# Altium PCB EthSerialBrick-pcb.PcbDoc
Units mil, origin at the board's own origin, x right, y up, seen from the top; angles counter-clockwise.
Board outline 3550 x 3775 mil, 4 copper layers (Top Layer, Internal Plane 1, Internal Plane 2, Bottom Layer); 26 components, 31 nets, 202 pads, 3 vias.
Unrouted connection lines stored in the file: 30.
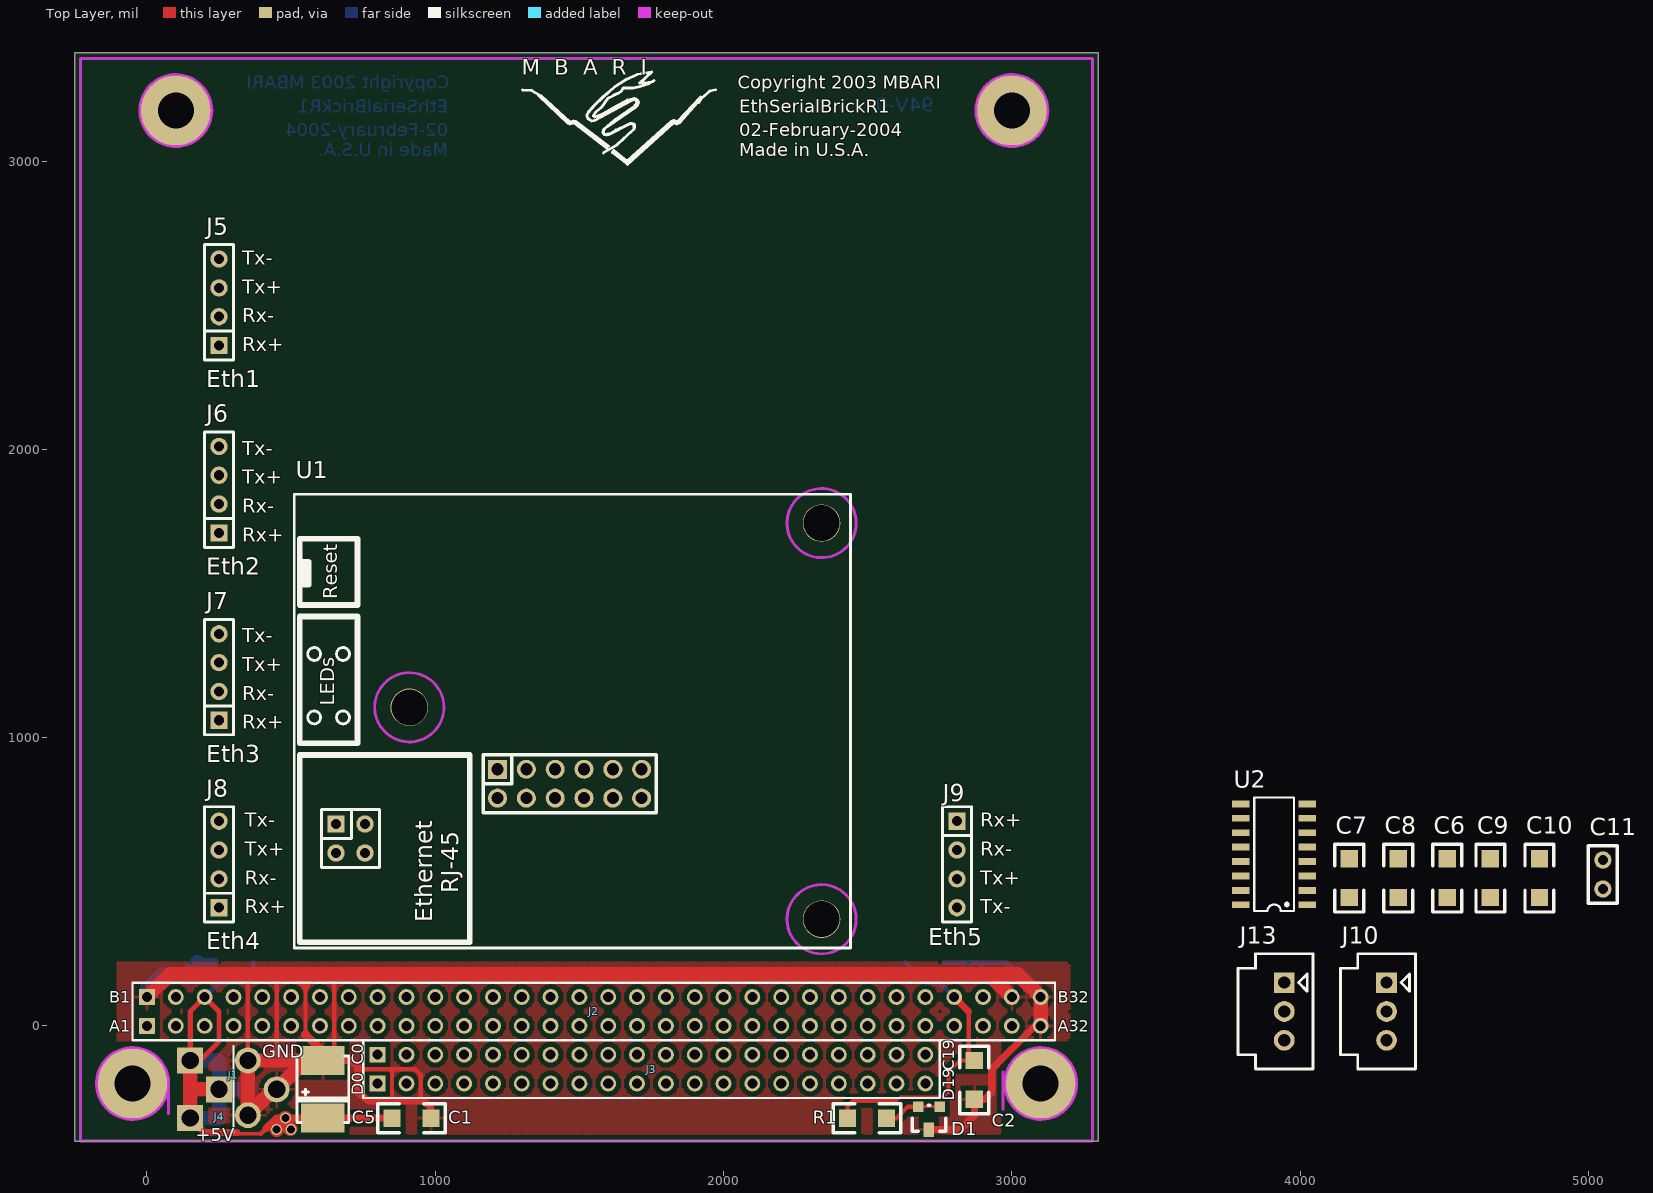
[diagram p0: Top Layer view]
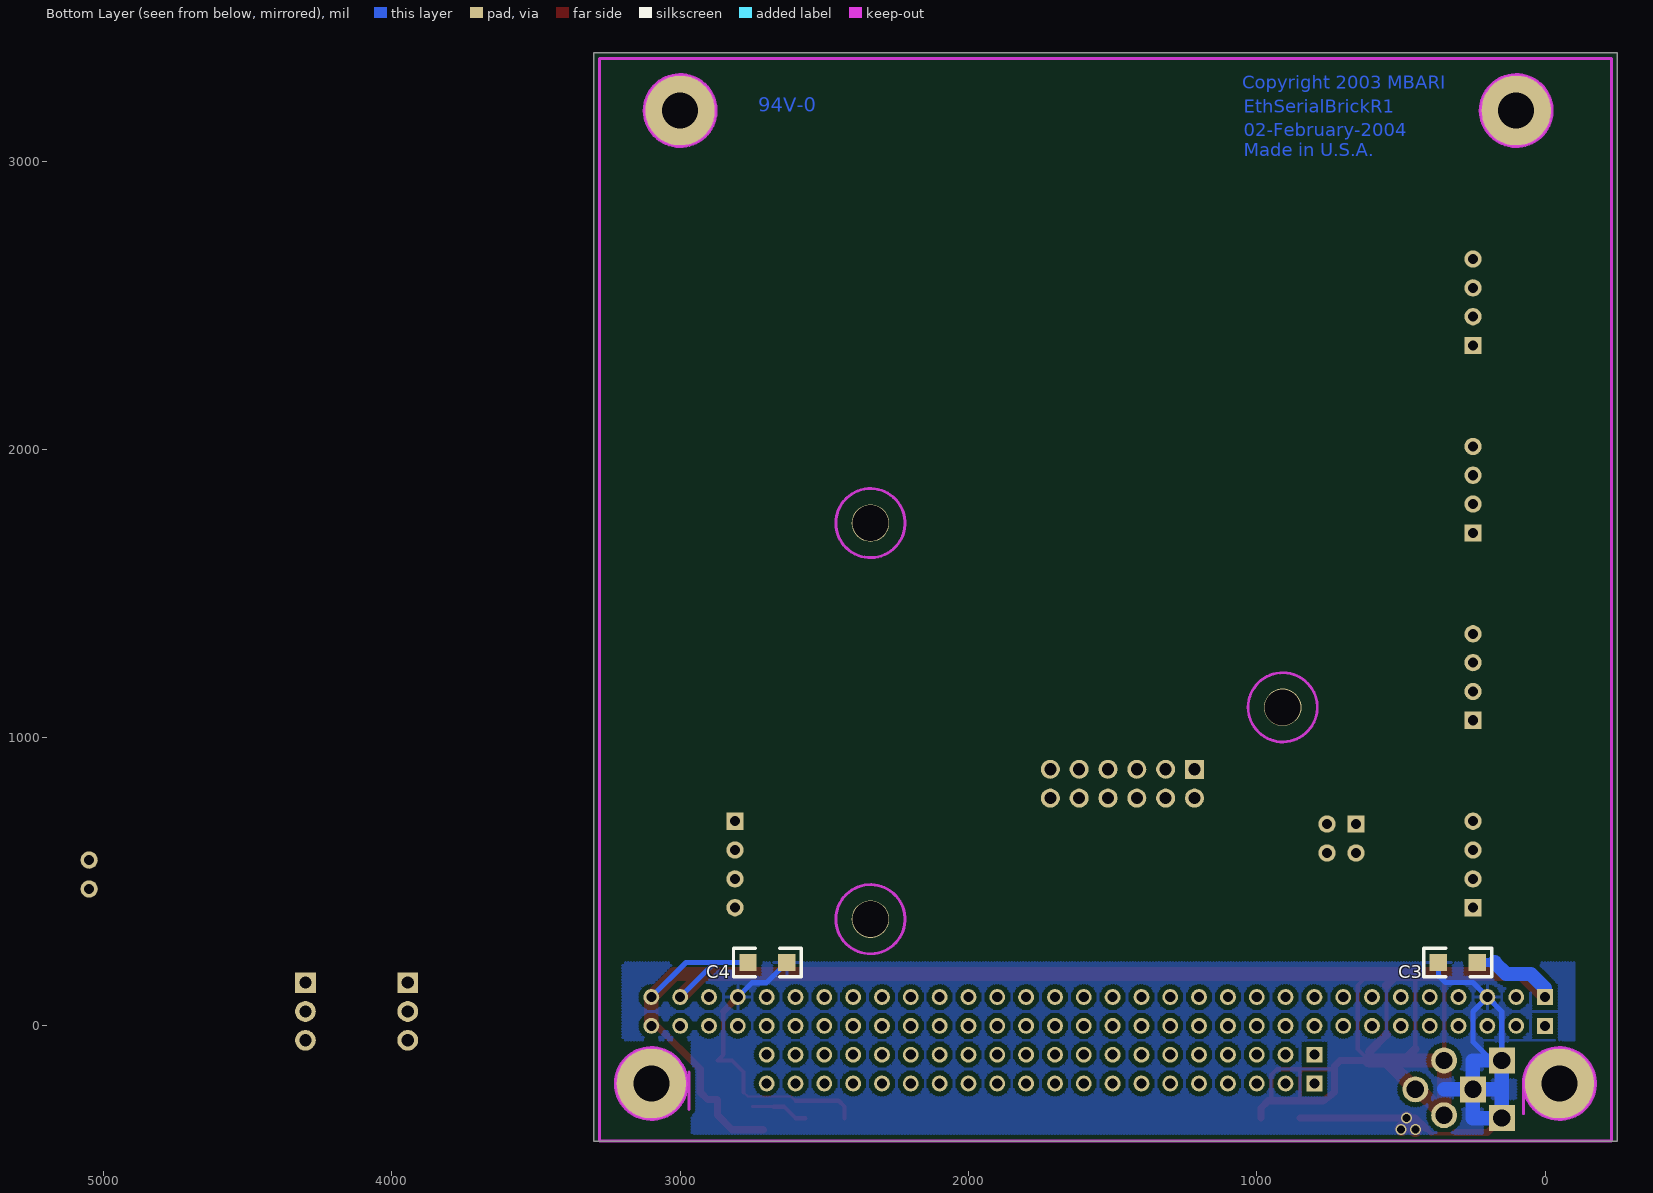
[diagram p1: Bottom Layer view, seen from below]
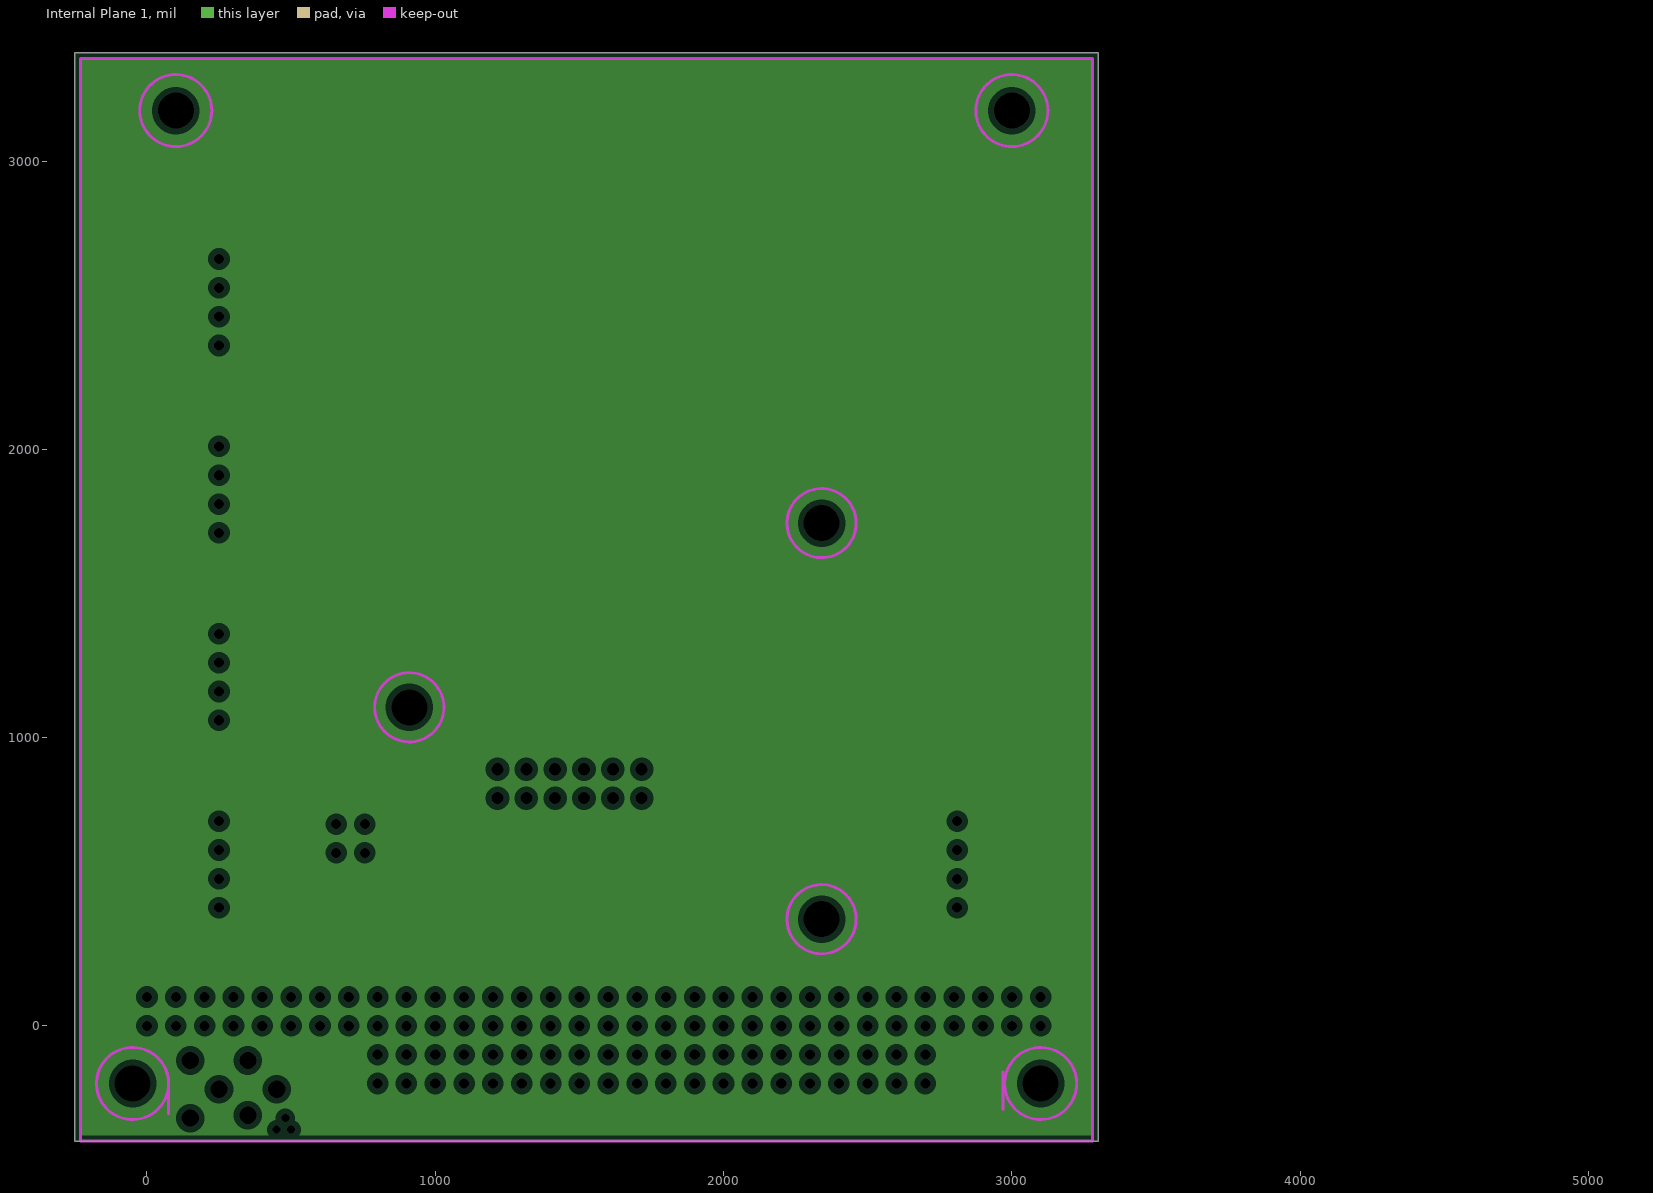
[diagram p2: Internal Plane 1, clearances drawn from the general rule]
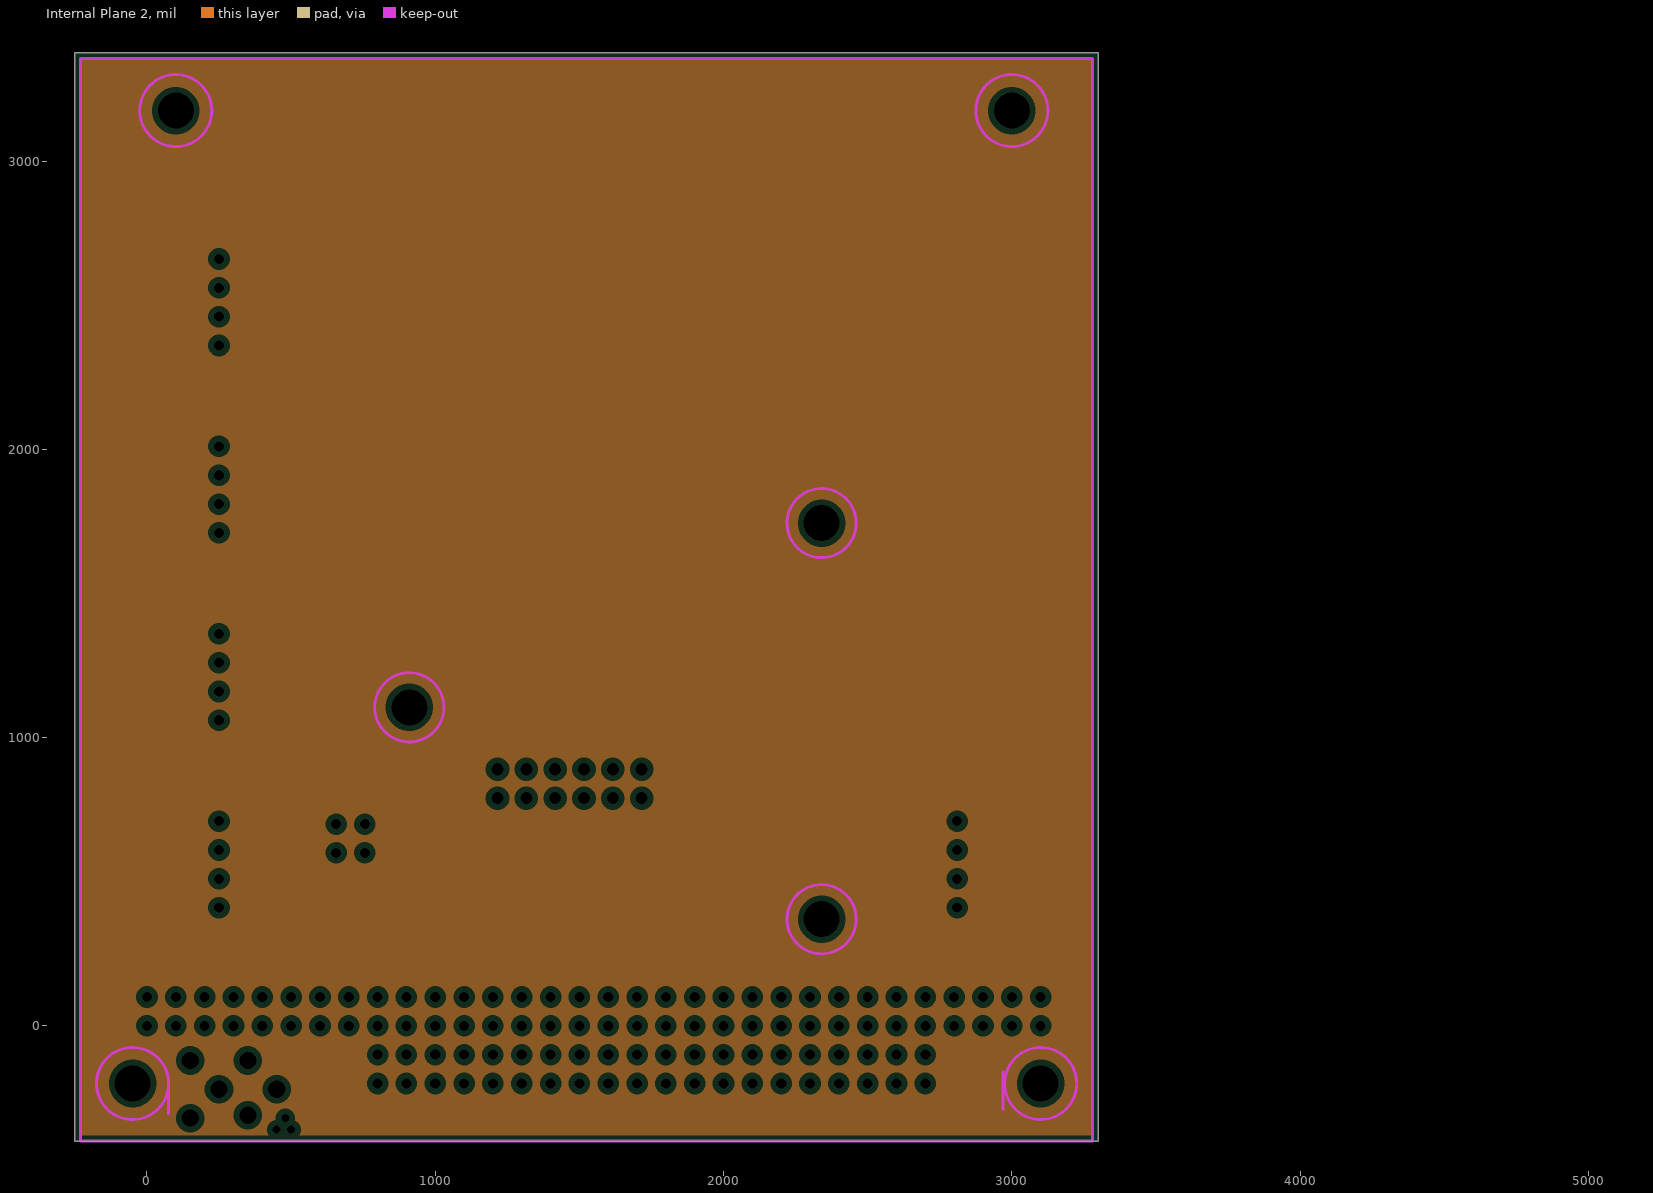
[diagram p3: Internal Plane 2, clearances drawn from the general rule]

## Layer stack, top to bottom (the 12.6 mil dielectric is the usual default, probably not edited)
Top Layer: signal copper 1.4
Dielectric: dielectric 12.6, FR-4, Dk 4.8
Internal Plane 1: plane copper 1.4
Dielectric: dielectric 12.6, FR-4, Dk 4.8
Internal Plane 2: plane copper 1.4
Dielectric: dielectric 12.6, FR-4, Dk 4.8
Bottom Layer: signal copper 1.4

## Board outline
-250,-400 -250,3375 3300,3375 3300,-400

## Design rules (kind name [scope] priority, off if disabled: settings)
Clearance Clearance_poly [InPolygon] p1: gap=16 // poly
Clearance [All] p2: gap=13
ComponentClearance [All] p1: gap=10 collisioncheckmode=0
FanoutControl Fanout_Small [(CompPinCount < 5)] p1: bgadir=Out bgaviamode=Centered fanoutstyle=Auto fanoutdirection=OutThenIn viagrid=1 // Fanout_Small (Default Rule)
FanoutControl Fanout_Default [All] p2: bgadir=Out bgaviamode=Centered fanoutstyle=Auto fanoutdirection=Alternating viagrid=1 // Fanout_Default (Default Rule)
FanoutControl Fanout_BGA [IsBGA] p4: bgadir=Out bgaviamode=Centered fanoutstyle=Auto fanoutdirection=Alternating viagrid=1 // Fanout_BGA (Default Rule)
FanoutControl Fanout_LCC [IsLCC] p5: bgadir=Out bgaviamode=Centered fanoutstyle=Auto fanoutdirection=Alternating viagrid=1 // Fanout_LCC (Default Rule)
HoleSize [All] p1: absolutevalues=TRUE maxlimit=152 minlimit=1 maxpercent=80.000 minpercent=20.000
PlaneClearance [All] p1: clearance=20
PlaneConnect [All] p1: planeconnectstyle=Relief reliefexpansion=20 reliefentries=4 reliefconductorwidth=10 reliefairgap=10
PolygonConnect [All] p1: connectstyle=Relief reliefconductorwidth=10 reliefentries=4 polygonreliefangle="90 Angle"
RoutingLayers [All] p1: top layer=Horizontal bottom layer=Vertical
RoutingVias [All] p1: holewidth=35 width=52 viastyle="Through Hole" minholewidth=28 minwidth=32 maxholewidth=86 maxwidth=72
SolderMaskExpansion [All] p1: expansion=4
TestPointUsage [All] p1: valid=0 allowmultiple=FALSE
Testpoint [All] p1: side=15 testpointundercomponent=TRUE minsize=40 maxsize=100 preferedsize=60 minholesize=0 maxholesize=40 preferedholesize=32 testpointgrid=1 style=1023 order=-539222988
Width [All] p1: maxlimit=250 minlimit=8 preferedwidth=12 toplayer_prefwidth=15 bottomlayer_prefwidth=50 minimp=50.000000 maximp=50.000000 favimp=50.000000
9 further rules are at their usual default settings.

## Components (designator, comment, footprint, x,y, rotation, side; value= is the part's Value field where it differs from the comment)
C1 "0.1uF" 1206 850,-320 r0 top
C2 "0.1uF" 1206 2870,-120 r270 top
C3 "0.1uF" 1206 370,220 r180 bottom
C4 "0.1uF" 1206 2630,220 r0 bottom
C5 "47uF" 6032POL 610,-320 r90 top
C6 "0.1uF" 1206 4510,445 r90 top
C7 "0.1uF" 1206 4170,445 r90 top
C8 "0.1uF" 1206 4340,445 r90 top
C9 "0.1uF" 1206 4660,445 r90 top
C10 "0.1uF" 1206 4830,445 r90 top
C11 "0.1uF" RAD0.1 5050,475 r90 top
D1 "LED" SOT-23 2750,-280 r180 top
J1 "Power" SIP4#1 150,-120 r0 top
J2 "PC104-AB" PC104-AB 0,0 r0 top locked
J3 "PC104-CD" PC104-CD 800,-200 r0 top locked
J4 "PowHD" SIP2 225,-765 r90 top
J5 "Eth1" SIP4#2 250,2360 r90 top locked
J6 "Eth2" SIP4#2 250,1710 r90 top locked
J7 "Eth3" SIP4#2 250,1060 r90 top locked
J8 "Eth4" SIP4#2 250,410 r90 top locked
J9 "Eth5" SIP4#2 2810,710 r270 top locked
J10 "Ser1" CGRID3 4300,150 r90 top
J13 "Ser2" CGRID3 3945,150 r90 top
R1 "510" 1206 2430,-320 r0 top
U1 "COBOX-MICRO" COBOX-MICRO 2440,270 r90 top
U2 "MAX232" SOIC-16-0.15W 4025,420 r90 top

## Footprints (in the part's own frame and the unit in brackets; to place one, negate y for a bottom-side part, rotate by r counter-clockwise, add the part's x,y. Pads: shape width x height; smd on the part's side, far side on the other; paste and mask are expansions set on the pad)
1206 [mil]
  rect 60x60 smd: 1(0,0) 2(135,0)
  silkscreen extent -50,-50 185,50
6032POL [mil]
  rect 100x150 smd: 1(0,0) 2(200,0)
  silkscreen extent -15,-90 215,90
CGRID3 [mil]
  rect 72x72 hole 42: 1(0,0)
  round 72 hole 42: 2(-100,0) 3(-200,0)
  silkscreen extent -300,-100 100,160
COBOX-MICRO [mil]
  round 130 hole 125: 0(100,100) 0(835,1530) 0(1474,100)
  rect 66x66 hole 42: 1(620,1224)
  round 66 hole 42: 2(520,1224) 3(620,1124) 4(520,1124) 5(620,1024) 6(520,1024) 7(620,924) 8(520,924) 9(620,824) 10(520,824) 11(620,724) 12(520,724)
  rect 60x60 hole 35: 21(430,1784)
  round 60 hole 35: 22(430,1684) 23(330,1784) 24(330,1684)
  Keep-Out Layer circle w10: c835,1530 r120
  Keep-Out Layer circle w10: c1474,100 r120
  Keep-Out Layer circle w10: c100,100 r120
  silkscreen extent 0,0 1574,1929
PC104-AB [mil] "PC/104 A&B rails"
  rect 55x55 hole 35: A1(0,0) B1(0,100)
  round 55 hole 35: A2(100,0) A3(200,0) A4(300,0) A5(400,0) A6(500,0) A7(600,0) A8(700,0) A9(800,0) A10(900,0) A11(1000,0) A12(1100,0) A13(1200,0) A14(1300,0) A15(1400,0) A16(1500,0) A17(1600,0) A18(1700,0) A19(1800,0) A20(1900,0) A21(2000,0) A22(2100,0) A23(2200,0) A24(2300,0) A25(2400,0) A26(2500,0) A27(2600,0) A28(2700,0) A29(2800,0) A30(2900,0) A31(3000,0) A32(3100,0) B2(100,100) B3(200,100) B4(300,100) B5(400,100) B6(500,100) B7(600,100) B8(700,100) B9(800,100) B10(900,100) B11(1000,100) B12(1100,100) B13(1200,100) B14(1300,100) B15(1400,100) B16(1500,100) B17(1600,100) B18(1700,100) B19(1800,100) B20(1900,100) B21(2000,100) B22(2100,100) B23(2200,100) B24(2300,100) B25(2400,100) B26(2500,100) B27(2600,100) B28(2700,100) B29(2800,100) B30(2900,100) B31(3000,100) B32(3100,100)
  silkscreen extent -50,-50 3150,150
PC104-CD [mil] "PC/104 C&D rails"
  rect 55x55 hole 35: C0(0,100) D0(0,0)
  round 55 hole 35: C1(100,100) C2(200,100) C3(300,100) C4(400,100) C5(500,100) C6(600,100) C7(700,100) C8(800,100) C9(900,100) C10(1000,100) C11(1100,100) C12(1200,100) C13(1300,100) C14(1400,100) C15(1500,100) C16(1600,100) C17(1700,100) C18(1800,100) C19(1900,100) D1(100,0) D2(200,0) D3(300,0) D4(400,0) D5(500,0) D6(600,0) D7(700,0) D8(800,0) D9(900,0) D10(1000,0) D11(1100,0) D12(1200,0) D13(1300,0) D14(1400,0) D15(1500,0) D16(1600,0) D17(1700,0) D18(1800,0) D19(1900,0)
  silkscreen extent -50,-50 1950,150
RAD0.1 [mil]
  round 60 hole 35: 1(0,0) 2(100,0)
  silkscreen extent -50,-50 150,50
SIP2 [mil]
  rect 90x90 hole 59.5: 1(445,75)
  round 90 hole 59.5: 2(455,-125)
SIP4#1 [mil]
  rect 90x90 hole 59.5: 1(0,0) 2(100,-100)
  round 90 hole 59.5: 3(200,0) 4(300,-100)
  silkscreen extent 150,-150 150,50
SIP4#2 [mil]
  rect 60x60 hole 35: 1(0,0)
  round 60 hole 35: 2(100,0) 3(200,0) 4(300,0)
  silkscreen extent -50,-50 350,50
SOIC-16-0.15W [mm] "SOIC-16 0.15\"Wide 1.27mm Pitch"
  rect 0.6x1.55 smd: 1(0,0) 2(1.27,0) 3(2.54,0) 4(3.81,0) 5(5.08,0) 6(6.35,0) 7(7.62,0) 8(8.89,0) 9(8.89,5.85) 10(7.62,5.85) 11(6.35,5.85) 12(5.08,5.85) 13(3.81,5.85) 14(2.54,5.85) 15(1.27,5.85) 16(0,5.85)
  silkscreen extent -0.55,1.18 9.44,4.67
SOT-23 [mil]
  rect 36x36 smd: 1(0,0) 2(75,0)
  rect 36x50 smd: 3(38,80)
  silkscreen extent -20,-5 95,85

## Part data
C1 C2 C3 C4 C6 C7 C8 C9 C10: library part CAPACITOR, "Capacitor"
C5: library part "CAPACITOR POL", "Capacitor"
C11: library part Cap, "Capacitor"
J1: library part CON4, "Connector"
J2: "PC/104 A&B rails"
J3: "PC/104 C&D rails"
J4: library part CON2, "Connector"
J5 J6 J7 J8 J9: library part CON4, "Connector 4 pin"
J10 J13: library part CON3, "Connector"
R1: library part RESISTOR, "Resistor"
U1: "CoBox Micro Terminal Server"
U2: "MAX232 Communications Chip"

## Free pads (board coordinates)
  round 250 hole 125: 0(-50,-200) 0(100,3175) 0(3000,3175) 0(3100,-200)

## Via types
v1: diameter 38, hole 28, Top Layer to Bottom Layer, 3 vias

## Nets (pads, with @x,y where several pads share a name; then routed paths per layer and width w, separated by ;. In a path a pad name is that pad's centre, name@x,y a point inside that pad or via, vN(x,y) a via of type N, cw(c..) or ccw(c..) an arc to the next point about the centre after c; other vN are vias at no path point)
GND: C1.2 C2.2 C3.2 C4.2 C5.2 C7.2 C9.1 C11.1 D1.3 J1.3 J1.4 J2.A32 J2.B1 J2.B31 J2.B32 J4.2 J10.3 J13.3 U1.2 U2.15 | length 7957.3
  Top Layer w15: J1.3 350,180 ; 440,180 450,170 450,-80 ; 550,-30 550,140 ; C5.2@610,-90 C5.2 650,-80 650,140 610,180 ; 730,-150 840,-150 ; 850,-260 850,-160 840,-150 ; 950,-260 950,-170 930,-150 840,-150
  Top Layer w25: C5.2 710,-120 730,-140 730,-220 730,-230 770,-260 960,-260 985,-285 C1.2 ; D1.3 2820,-360 2870,-310 C2.2 2905,-255 2930,-230 2930,-150 3080,0 J2.A32
  Top Layer w30: 450,-80 490,-120 C5.2 ; 510,180 550,140 ; 550,-30 C5.2@610,-90
  Top Layer w50: J2.B1 80,180 510,180 610,180 3020,180 J2.B32 J2.A32 ; C5.2@550,-120 J1.4 440,-220 J4.2 J1.3 C5.2 ; 2920,180 J2.B31
  Bottom Layer w18: C4.2 2880,220 ; J2.B31 2880,220 ; J2.B32 2980,220 2880,220
  Bottom Layer w30: 175,220 C3.2
  Bottom Layer w50: J2.B1 0,130 50,180 135,180 175,220
NetC6_1: C6.1 U2.2
NetC8_1: C8.1 U2.1
NetC8_2: C8.2 U2.3
NetC9_2: C9.2 U2.6
NetC10_1: C10.1 U2.4
NetC10_2: C10.2 U2.5
NetD1_2: D1.2 R1.2 | length 126.6
  Top Layer w15: R1.2 2600,-320 2640,-280 D1.2
NetJ6_1: J6.1
NetJ6_2: J6.2
NetJ6_3: J6.3
NetJ6_4: J6.4
NetJ8_1: J8.1 U1.23
NetJ8_2: J8.2 U1.24
NetJ8_3: J8.3 U1.21
NetJ8_4: J8.4 U1.22
NetJ10_1: J10.1 U2.14
NetJ10_2: J10.2 U2.13
NetJ11_1: 
NetJ11_2: 
NetJ11_3: 
NetJ12_1: 
NetJ12_2: 
NetJ12_3: 
NetJ13_1: J13.1 U2.7
NetJ13_2: J13.2 U2.8
NetU1_3: U1.3 U2.12
NetU1_4: U1.4 U2.11
NetU1_11: U1.11 U2.9
NetU1_12: U1.12 U2.10
VCC: C1.1 C2.1 C3.1 C4.1 C5.1 C6.2 C7.1 C11.2 J1.1 J1.2 J2.B3 J2.B29 J4.1 R1.1 U1.1 U2.16 | length 4326.1
  Top Layer w8: 2615,-245 2765,-245 2780,-230
  Top Layer w10: 2600,-260 2615,-245
  Top Layer w13: 317.18,-374.5 394.5,-374.5
  Top Layer w15: 312.18,-369.5 317.18,-374.5 ; 394.5,-374.5 414,-355 ; R1.1 2430,-280 2450,-260 2600,-260 ; 2780,-230 2780,-160 2820,-120 C2.1 2850,-100 2850,50
  Top Layer w18: J1.1 185,-120 250,-55 250,50 J2.B3 150,50 J1.1
  Top Layer w25: J4.1 199.5,-369.5 312.18,-369.5 ; 414,-355 449,-320 C5.1 ; C5.1@610.5,-319.5 C5.1 ; C1.1 C5.1 ; J2.B29 2850,50
  Top Layer w50: J4.1 J1.1 ; 150,-225 155,-220 J1.2 ; v1(450,-360) 450,-357 v1@480,-327 ; v1(480,-320) 480,-340 v1@497,-357
  Bottom Layer w18: C3.1 370,175 345,150 250,150 J2.B3 ; C4.1 2700.5,149.5 2750.5,149.5 J2.B29 ; J2.B3 250,50 250,-55 185,-120 J1.1 150,50 J2.B3
  Bottom Layer w50: 150,-220 J1.2 ; 350,-220 J1.2 ; J1.2 250,-120 J1.1 J4.1 250,-320 J1.2
  other v1: 500,-360
pads on no net: D1.1 J2.A1 J2.A2 J2.A3 J2.A4 J2.A5 J2.A6 J2.A7 J2.A8 J2.A9 J2.A10 J2.A11 J2.A12 J2.A13 J2.A14 J2.A15 J2.A16 J2.A17 J2.A18 J2.A19 J2.A20 J2.A21 J2.A22 J2.A23 J2.A24 J2.A25 J2.A26 J2.A27 J2.A28 J2.A29 J2.A30 J2.A31 J2.B2 J2.B4 J2.B5 J2.B6 J2.B7 J2.B8 J2.B9 J2.B10 J2.B11 J2.B12 J2.B13 J2.B14 J2.B15 J2.B16 J2.B17 J2.B18 J2.B19 J2.B20 J2.B21 J2.B22 J2.B23 J2.B24 J2.B25 J2.B26 J2.B27 J2.B28 J2.B30 J3.C0 J3.C1 J3.C2 J3.C3 J3.C4 J3.C5 J3.C6 J3.C7 J3.C8 J3.C9 J3.C10 J3.C11 J3.C12 J3.C13 J3.C14 J3.C15 J3.C16 J3.C17 J3.C18 J3.C19 J3.D0 J3.D1 J3.D2 J3.D3 J3.D4 J3.D5 J3.D6 J3.D7 J3.D8 J3.D9 J3.D10 J3.D11 J3.D12 J3.D13 J3.D14 J3.D15 J3.D16 J3.D17 J3.D18 J3.D19 J5.1 J5.2 J5.3 J5.4 J7.1 J7.2 J7.3 J7.4 J9.1 J9.2 J9.3 J9.4 U1.0 U1.5 U1.6 U1.7 U1.8 U1.9 U1.10
copper on no net: | length 75
  Top Layer w10: 2675,-280 2750,-280

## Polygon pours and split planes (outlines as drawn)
GND on Top Layer (hatched 90Degree grid 10 track 10, remove dead copper): -100,220 3200,220 3200,-50 2960,-50 2960,-400 90,-400 90,-50 -100,-50
VCC on Bottom Layer (hatched 90Degree grid 10 track 10, remove dead copper): -100,220 3200,220 3200,-50 2960,-50 2960,-400 90,-400 90,-50 -100,-50
no net on Internal Plane 1 (split plane): -229.99,-379.99 -229.99,3354.98 3279.98,3354.98 3279.98,-379.99
no net on Internal Plane 2 (split plane): -229.99,-379.99 -229.99,3354.98 3279.98,3354.98 3279.98,-379.99

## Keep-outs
Keep-Out Layer:
  circle w10: c3100,-200 r125
  circle w10: c3000,3175 r125
  circle w10: c100,3175 r125
  circle w10: c-50,-200 r125
  lines w10: 75,-305 75,-200 ; 2970,-290 2970,-160 ; -230,-400 -230,3355 3280,3355 3280,-400 -230,-400
  text ".GKO" at 14990,-940 h90

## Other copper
Top Layer:
  text ".GTL" at 14990,-940 h90
Bottom Layer:
  text "Copyright 2003 MBARI" at 1050,3250 h45
  text "94V-0" at 2730,3170 h50
  text "EthSerialBrickR1" at 1045,3166.68 h45
  text "02-February-2004" at 1045,3086.68 h45
  text "Made in U.S.A." at 1045,3016.68 h45
  text ".GBL" at 14990,-940 h90

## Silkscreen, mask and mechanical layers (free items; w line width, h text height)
Top Overlay:
  lines w8: 300,-370 300,-270
  lines w10: 1303,3246 1335,3244 1366,3226 1467,3135 1480,3139 1487,3138 1601,3051 ; 1358,3228 1461,3131 ; 1466,3128 1481,3132 1596,3044 ; 1583,3028 1629,3055 1688,3109 1691,3116 1691,3126 1689,3129 1683,3130 1676,3130 ; 1614,3030 1661,2993 ; 1618,3037 1666,2999 1818,3137 1827,3141 1841,3136 1920,3222 1923,3217 1952,3243 1972,3247 ; 1690,3115 1690,3123 1688,3127 1683,3129 1676,3130 ; 1824,3133 1839,3128 ; 1846,3132 1911,3205 ; 1914,3202 1920,3211 ; 1676,3130 1602,3092 1594,3090 1587,3092 1583,3099 1584,3105 1588,3113 1599,3121 1694,3186 1702,3195 1705,3202 1703,3207 1701,3211 1697,3213 1690,3213 1680,3210 1552,3140 1542,3139 1534,3144 1529,3148 1526,3155 1527,3161 1531,3169 1553,3194 1581,3221 1620,3255 1663,3283 1702,3301 1751,3309 1708,3270 1725,3270 1754,3275 1759,3279 1742,3269 1726,3264 1710,3258 1687,3253 1652,3253 1645,3242 1632,3234 1617,3227 1599,3217 1577,3187 1559,3172 1548,3157 1552,3153 1582,3163 1630,3191 1666,3211 1690,3217 1696,3215 1700,3204 1689,3188 1621,3141 1583,3109 1582,3097 1586,3092 1609,3096 1626,3107 1669,3127 1676,3130 ; 1667,2988 1826,3133 1667,2988
  text "M  B  A  R  I" at 1300,3300 h55
  text "Copyright 2003 MBARI" at 2050,3250 h45
  text "EthSerialBrickR1" at 2055,3166.68 h45
  text "02-February-2004" at 2055,3086.68 h45
  text "Made in U.S.A." at 2055,3016.68 h45
  text "Tx-" at 330,2640 h50
  text "Tx+" at 330,2540 h50
  text "Rx-" at 330,2440 h50
  text "Rx+" at 330,2340 h50
  text "Tx-" at 330,1980 h50
  text "Tx+" at 330,1880 h50
  text "Rx-" at 330,1780 h50
  text "Rx+" at 330,1680 h50
  text "Tx-" at 330,1330 h50
  text "Tx+" at 330,1230 h50
  text "Rx-" at 330,1130 h50
  text "Rx+" at 330,1030 h50
  text "Tx-" at 340,690 h50
  text "Rx+" at 2890,690 h50
  text "Tx+" at 340,590 h50
  text "Rx-" at 2890,590 h50
  text "Rx-" at 340,490 h50
  text "Tx+" at 2890,490 h50
  text "Rx+" at 340,390 h50
  text "Tx-" at 2890,390 h50
  text "GND" at 400,-110 h45
  text "+5V" at 170,-400 h45
  text ".GTO" at 14990,-940 h90
Bottom Overlay:
  text ".GBO" at 15000,-940 h90
Top Solder:
  text ".GTS" at 15000,-940 h90
Bottom Solder:
  text ".GBS" at 15000,-940 h90
Drill Guide:
  text ".GG1" at 15000,-940 h90
Mechanical 4:
  the board outline again, w10
Mechanical 16:
  lines w5: -1050,1550 -850,1550 ; -1050,4300 -850,4300 ; -1050,7050 -850,7050 ; 1750,9200 1750,9400 ; 1785,-1200 1785,-1000 ; 4615,-1200 4615,-1000 ; 4615,9200 4615,9400 ; 7450,-1200 7450,-1000 ; 7450,9200 7450,9400 ; 9450,-400 15350,-400 ; 10280,-1200 10280,-1000 ; 10280,9200 10280,9400 ; 10850,-700 15350,-700 ; 10850,-100 12350,-100 ; 12350,-1000 12350,-400 12350,200 ; 13115,-1200 13115,-1000 ; 13115,9200 13115,9400 ; 14450,-1000 14450,-400 ; 15350,1550 15550,1550 ; 15350,4300 15550,4300 ; 15350,7050 15550,7050 ; 10850,-1000 10850,200 ; 10850,-1000 15350,-1000 ; 10850,-1000 9450,-1000 9450,200 10850,200 ; 10850,200 12350,200 ; 12350,200 15350,200 15350,-1000 ; 15350,-1000 15350,9200 -850,9200 -850,-1000 15350,-1000 ; -1050,-1200 15550,-1200 15550,9400 -1050,9400 -1050,-1200
  lines w10: 9783,46 9815,44 9846,26 9947,-65 9960,-61 9967,-62 10081,-149 ; 9838,28 9941,-69 ; 9946,-72 9961,-68 10076,-156 ; 10063,-172 10109,-145 10168,-91 10171,-84 10171,-74 10169,-71 10163,-70 10156,-70 ; 10094,-170 10141,-207 ; 10098,-163 10146,-201 10298,-63 10307,-59 10321,-64 10400,22 10403,17 10432,43 10452,47 ; 10170,-85 10170,-77 10168,-73 10163,-71 10156,-70 ; 10304,-67 10319,-72 ; 10326,-68 10391,5 ; 10394,2 10400,11 ; 10156,-70 10082,-108 10074,-110 10067,-108 10063,-101 10064,-95 10068,-87 10079,-79 10174,-14 10182,-5 10185,2 10183,7 10181,11 10177,13 10170,13 10160,10 10032,-60 10022,-61 10014,-56 10009,-52 10006,-45 10007,-39 10011,-31 10033,-6 10061,21 10100,55 10143,83 10182,101 10231,109 10188,70 10205,70 10234,75 10239,79 10222,69 10206,64 10190,58 10167,53 10132,53 10125,42 10112,34 10097,27 10079,17 10057,-13 10039,-28 10028,-43 10032,-47 10062,-37 10110,-9 10146,11 10170,17 10176,15 10180,4 10169,-12 10101,-59 10063,-91 10062,-103 10066,-108 10089,-104 10106,-93 10149,-73 10156,-70 ; 10147,-212 10306,-67 10147,-212
  text "1" at 351.34,9265 h70
  text "2" at 3177,9265 h70
  text "3" at 6002,9265 h70
  text "4" at 8843.01,9265 h70
  text "5" at 11677,9265 h70
  text "6" at 14512,9265 h70
  text "A" at -975,8422 h70
  text "A" at 15425,8422 h70
  text "B" at -975,5688.02 h70
  text "B" at 15425,5688.02 h70
  text "C" at -975,2907 h70
  text "C" at 15425,2907 h70
  text "M  B  A  R  I" at 9780,100 h55
  text "ENGINEER:" at 10900,100 h45
  text "TITLE:" at 12400,100 h45
  text "D" at -975,85 h70
  text "D" at 15425,85 h70
  text "Mark Sibenac" at 11410,70 h70
  text "Ethernet to Serial Brick" at 12750,-20 h90
  text "1 831 775 2028" at 11400,-70 h60
  text "PCB DESIGNER:" at 10900,-195 h45
  text "For use with Mapping AUV" at 12770,-240 h90
  text "Copyright      2003" at 9630,-250 h60
  text "Monterey Bay Aquarium Research Institute" at 9500,-360 h45
  text "DATE:" at 10900,-500 h45
  text "PART NO.:" at 12400,-500 h45
  text "REV:" at 14500,-500 h45
  text ".PRINT_DATE" at 10950,-620 h70
  text "1" at 14780,-620 h90
  text "EthSerialBrickR1" at 12760,-630 h60
  text "M.B.A.R.I." at 9530,-640 h100
  text "7700 Sandholdt Rd." at 9520,-740 h60
  text "FILE NAME:" at 10900,-800 h45
  text "DWG NO:" at 12400,-800 h45
  text "GERBER:" at 14500,-800 h45
  text "Moss Landing, CA 95039" at 9520,-850 h60
  text "100....." at 12760,-890 h60
  text ".PCB_FILE_NAME_NO_PATH" at 10950,-920 h70
  text ".GM16" at 14610,-930 h70
  text "Fax: 1 831 775 1646" at 9520,-950 h60
  text "1" at 351.34,-1135 h70
  text "2" at 3177,-1135 h70
  text "3" at 6002,-1135 h70
  text "4" at 8843.01,-1135 h70
  text "5" at 11677,-1135 h70
  text "6" at 14512,-1135 h70
Drill Drawing:
  text ".LEGEND" at 9495,470 h60
  text "Drill Drawing." at 9475,380 h60
  text ".GD1" at 14995,-940 h90

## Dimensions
-50,-200 to -250,-400 on Mechanical 4
-50,-200 to -250,-400 on Mechanical 4
-250,3375 to -250,-400 on Mechanical 4
-250,-400 to 3300,-400 on Mechanical 4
